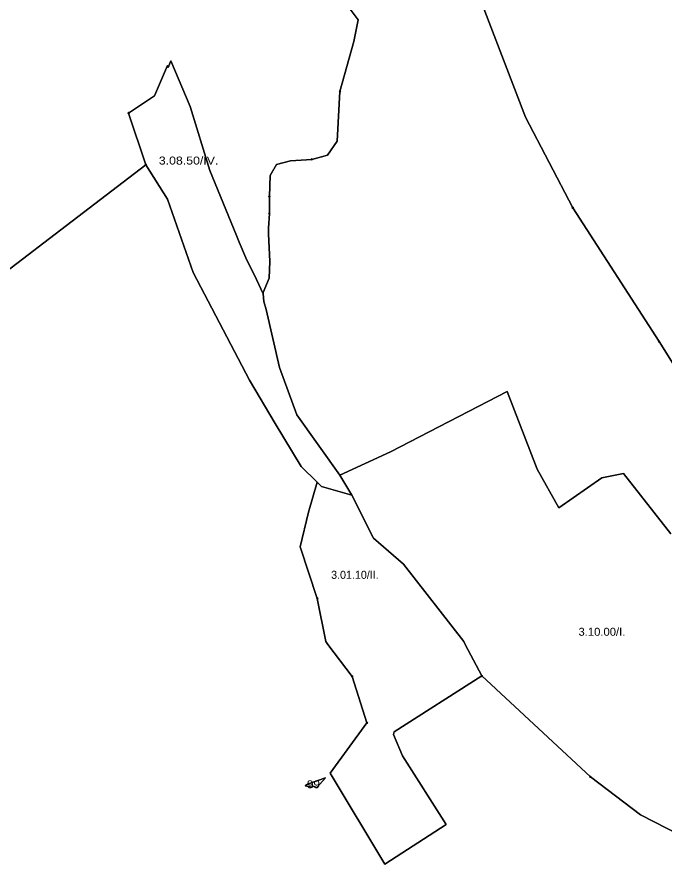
# Model space of a CAD drawing. Extents: x -650455 to -642254, y -1075222 to -1066610.
# Drawn here: x -647687 to -646878, y -1072281 to -1071216 of the extents above; entities that cross this region are included whole.
import ezdxf
from ezdxf.enums import TextEntityAlignment as Align

# ---------------------------------------------------------------- set-up
doc = ezdxf.new("R2010")
doc.units = 0
doc.header["$LTSCALE"] = 4
doc.header["$PDMODE"] = 32
doc.header["$PDSIZE"] = 2
for name, color, linetype, lineweight in [('1', 7, 'Continuous', 25), ('11', 7, 'Continuous', 13), ('12', 7, 'Continuous', 13), ('14', 7, 'Continuous', 13)]:
    doc.layers.add(name, color=color, linetype=linetype, lineweight=lineweight)
doc.layers.add('2', color=7, linetype='Continuous')

msp = doc.modelspace()

# ---------------------------------------------------------------- linework, layer by layer
at = {"layer": '1'}
for points in [[(-647412.981, -1071489.088), (-647446.149, -1071408.082), (-647470.706, -1071328.032), (-647494.813, -1071270.777), (-647498.258, -1071279.39), (-647499.23, -1071276.872), (-647515.389, -1071314.575), (-647547.706, -1071336.12), (-647526.161, -1071400.754), (-647800.855, -1071610.814), (-647801.949, -1071610.478), (-647870.875, -1071589.27), (-647903.192, -1071562.339), (-647919.351, -1071530.022), (-647913.965, -1071497.705), (-647903.192, -1071460.002), (-647881.648, -1071406.14), (-647897.806, -1071357.665), (-647773.924, -1071271.486), (-647788.736, -1071241.189), (-647806.937, -1071195.687)], [(-647277.051, -1071198.1), (-647260.893, -1071219.644), (-647266.279, -1071246.575), (-647283.784, -1071309.189), (-647287.224, -1071371.123), (-647299.444, -1071388.627), (-647318.899, -1071394.049), (-647345.688, -1071395.963), (-647362.91, -1071400.428), (-647370.883, -1071414.141), (-647371.84, -1071440.612), (-647371.84, -1071461.661), (-647372.796, -1071479.84), (-647372.796, -1071487.175), (-647371.521, -1071521.618), (-647372.159, -1071542.667), (-647379.813, -1071560.208), (-647379.646, -1071562.215), (-647388.105, -1071543.943), (-647401.5, -1071517.154), (-647409.473, -1071497.38), (-647412.981, -1071489.088)], [(-646870.396, -1071861.944), (-646929.643, -1071786.538), (-646956.574, -1071791.924), (-647010.436, -1071829.627), (-647037.367, -1071781.152), (-647075.07, -1071684.201), (-647220.496, -1071759.607), (-647283.784, -1071788.558), (-647337.645, -1071713.152), (-647359.19, -1071653.904), (-647375.906, -1071581.469), (-647378.856, -1071571.689), (-647379.646, -1071562.215), (-647379.813, -1071560.208), (-647372.159, -1071542.667), (-647371.521, -1071521.618), (-647372.796, -1071487.175), (-647372.796, -1071479.84), (-647371.84, -1071461.661), (-647371.84, -1071440.612), (-647370.883, -1071414.141), (-647362.91, -1071400.428), (-647345.688, -1071395.963), (-647318.899, -1071394.049), (-647299.444, -1071388.627), (-647287.224, -1071371.123), (-647283.784, -1071309.189), (-647266.279, -1071246.575), (-647260.893, -1071219.644), (-647277.051, -1071198.1)], [(-647052.179, -1071341.506), (-647104.694, -1071203.486)], [(-647104.694, -1071203.486), (-647052.179, -1071341.506), (-646992.931, -1071454.616), (-646885.208, -1071621.587), (-646804.415, -1071750.855)], [(-646804.415, -1071750.855), (-646885.208, -1071621.587), (-646992.931, -1071454.616), (-647052.179, -1071341.506)], [(-647800.855, -1071610.814), (-647526.161, -1071400.754), (-647499.23, -1071443.843), (-647466.913, -1071535.408), (-647396.893, -1071670.062), (-647364.576, -1071723.924)], [(-646859, -1072238.5), (-646908.5, -1072213.001), (-646971, -1072165.5), (-647106.5, -1072039.5), (-647127.153, -1072000), (-647128.931, -1071996.598), (-647204.338, -1071899.647), (-647242.041, -1071867.33), (-647268.972, -1071813.469), (-647283.784, -1071788.558), (-647220.496, -1071759.607), (-647075.07, -1071684.201), (-647037.367, -1071781.152), (-647010.436, -1071829.627), (-646956.574, -1071791.924), (-646929.643, -1071786.538), (-646870.396, -1071861.944)], [(-647364.576, -1071723.924), (-647332.259, -1071777.785), (-647312.093, -1071797.421)], [(-647312.093, -1071797.421), (-647322.833, -1071835.013), (-647333.606, -1071878.103), (-647312.061, -1071942.737), (-647301.289, -1071996.598), (-647298.718, -1072000), (-647268.5, -1072040), (-647250, -1072098), (-647296, -1072161), (-647227.5, -1072274.5), (-647151, -1072225.001), (-647205.5, -1072139.501), (-647217, -1072112.5), (-647216, -1072109.5), (-647106.5, -1072039.5), (-646971, -1072165.5), (-646908.5, -1072213.001), (-646859, -1072238.5)]]:
    msp.add_lwpolyline(points, dxfattribs=at)
for points in [[(-647379.646, -1071562.215), (-647378.856, -1071571.689), (-647375.906, -1071581.469), (-647359.19, -1071653.904), (-647337.645, -1071713.152), (-647283.784, -1071788.558), (-647268.972, -1071813.469), (-647306.675, -1071802.696), (-647312.093, -1071797.421), (-647332.259, -1071777.785), (-647364.576, -1071723.924), (-647396.893, -1071670.062), (-647466.913, -1071535.408), (-647499.23, -1071443.843), (-647526.161, -1071400.754), (-647547.706, -1071336.12), (-647515.389, -1071314.575), (-647499.23, -1071276.872), (-647498.258, -1071279.39), (-647494.813, -1071270.777), (-647470.706, -1071328.032), (-647446.149, -1071408.082), (-647412.981, -1071489.088), (-647409.473, -1071497.38), (-647401.5, -1071517.154), (-647388.105, -1071543.943)], [(-647268.972, -1071813.469), (-647242.041, -1071867.33), (-647204.338, -1071899.647), (-647128.931, -1071996.598), (-647127.153, -1072000), (-647106.5, -1072039.5), (-647216, -1072109.5), (-647217, -1072112.5), (-647205.5, -1072139.501), (-647151, -1072225.001), (-647227.5, -1072274.5), (-647296, -1072161), (-647250, -1072098), (-647268.5, -1072040), (-647298.718, -1072000), (-647301.289, -1071996.598), (-647312.061, -1071942.737), (-647333.606, -1071878.103), (-647322.833, -1071835.013), (-647312.093, -1071797.421), (-647306.675, -1071802.696)], [(-647301.629, -1072166.951), (-647312.731, -1072178.69), (-647317.33, -1072176.99), (-647318.97, -1072178.43), (-647327.05, -1072176.85), (-647324.44, -1072174.5)], [(-647301.629, -1072166.951), (-647324.44, -1072174.5), (-647327.05, -1072176.85), (-647318.97, -1072178.43), (-647317.33, -1072176.99), (-647312.731, -1072178.69)]]:
    msp.add_lwpolyline(points, close=True, dxfattribs=at)
at = {"layer": '11'}
for points in [[(-647547.706, -1070654.771), (-647515.389, -1070730.177), (-647460.18, -1070837.227), (-647390.16, -1070966.495), (-647320.14, -1071068.832), (-647244.734, -1071176.555), (-647277.051, -1071198.1), (-647260.893, -1071219.644), (-647266.279, -1071246.575), (-647283.784, -1071309.189), (-647287.224, -1071371.123), (-647299.444, -1071388.627), (-647318.899, -1071394.049), (-647345.688, -1071395.963), (-647362.91, -1071400.428), (-647370.883, -1071414.141), (-647371.84, -1071440.612), (-647371.84, -1071461.661)], [(-646992.931, -1071454.616), (-647052.179, -1071341.506), (-647104.694, -1071203.486), (-647131.625, -1071160.397), (-647158.555, -1071128.08), (-647180.1, -1071041.901), (-647207.031, -1070971.881)], [(-647526.161, -1071400.754), (-647800.855, -1071610.814), (-647801.949, -1071610.478), (-647799.782, -1071650.366), (-647789.455, -1071675.321), (-647779.56, -1071698.124), (-647786.013, -1071719.637), (-647794.619, -1071750.616), (-647797.63, -1071786.328), (-647789.455, -1071836.453), (-647780.85, -1071882.921), (-647775.687, -1071897.12), (-647747.29, -1071974.351), (-647744.278, -1072000.167), (-647701.628, -1072109.378), (-647917.5, -1072238.5), (-647970, -1072276), (-647994, -1072324), (-648000.504, -1072347.414)], [(-647312.061, -1071942.737), (-647333.606, -1071878.103), (-647322.833, -1071835.013), (-647312.093, -1071797.421), (-647332.259, -1071777.785), (-647364.576, -1071723.924), (-647396.893, -1071670.062), (-647466.913, -1071535.408), (-647499.23, -1071443.843), (-647526.161, -1071400.754)], [(-646698.038, -1071931.964), (-646735.742, -1071888.875), (-646762.673, -1071818.855), (-646804.415, -1071750.855), (-646885.208, -1071621.587), (-646992.931, -1071454.616)], [(-647371.84, -1071461.661), (-647372.796, -1071479.84), (-647372.796, -1071487.175), (-647371.521, -1071521.618), (-647372.159, -1071542.667), (-647379.813, -1071560.208), (-647379.646, -1071562.215), (-647378.856, -1071571.689), (-647375.906, -1071581.469), (-647359.19, -1071653.904), (-647337.645, -1071713.152), (-647283.784, -1071788.558), (-647220.496, -1071759.607), (-647075.07, -1071684.201), (-647037.367, -1071781.152), (-647010.436, -1071829.627), (-646956.574, -1071791.924), (-646929.643, -1071786.538), (-646870.396, -1071861.944)], [(-646870.396, -1071861.944), (-646929.643, -1071786.538), (-646956.574, -1071791.924), (-647010.436, -1071829.627), (-647037.367, -1071781.152), (-647075.07, -1071684.201), (-647220.496, -1071759.607), (-647283.784, -1071788.558), (-647268.972, -1071813.469), (-647242.041, -1071867.33), (-647204.338, -1071899.647), (-647128.931, -1071996.598)], [(-647106.5, -1072039.5), (-647216, -1072109.5), (-647217, -1072112.5), (-647205.5, -1072139.501), (-647151, -1072225.001), (-647227.5, -1072274.5), (-647296, -1072161), (-647250, -1072098), (-647268.5, -1072040), (-647298.718, -1072000), (-647301.289, -1071996.598), (-647312.061, -1071942.737)], [(-647128.931, -1071996.598), (-647127.153, -1072000), (-647106.5, -1072039.5), (-646971, -1072165.5)], [(-646725, -1072227.5), (-646766, -1072244.501), (-646794, -1072249.501), (-646830.5, -1072247), (-646859, -1072238.5), (-646908.5, -1072213.001), (-646971, -1072165.5), (-647106.5, -1072039.5)], [(-646971, -1072165.5), (-646908.5, -1072213.001), (-646859, -1072238.5)]]:
    msp.add_lwpolyline(points, dxfattribs=at)
for p in [(-647526.161, -1071400.754), (-646992.931, -1071454.616), (-647371.84, -1071461.661), (-647312.061, -1071942.737), (-647106.5, -1072039.5), (-646971, -1072165.5)]:
    msp.add_point(p, dxfattribs=at)
at = {"layer": '12'}
msp.add_line((-647268.5, -1072040), (-647250, -1072098), dxfattribs=at)
for points in [[(-647283.784, -1071309.189), (-647266.279, -1071246.575), (-647260.893, -1071219.644), (-647277.051, -1071198.1), (-647244.734, -1071176.555), (-647320.14, -1071068.832), (-647390.16, -1070966.495), (-647460.18, -1070837.227), (-647515.389, -1070730.177), (-647547.706, -1070654.771), (-647558.478, -1070606.295), (-647585.409, -1070514.73), (-647601.567, -1070433.938), (-647606.954, -1070347.759), (-647628.498, -1070288.512)], [(-647547.706, -1071336.12), (-647515.389, -1071314.575), (-647499.23, -1071276.872), (-647498.258, -1071279.39), (-647494.813, -1071270.777), (-647470.706, -1071328.032), (-647446.149, -1071408.082), (-647412.981, -1071489.088), (-647409.473, -1071497.38), (-647401.5, -1071517.154), (-647388.105, -1071543.943), (-647379.646, -1071562.215), (-647379.813, -1071560.208), (-647372.159, -1071542.667), (-647371.521, -1071521.618), (-647372.796, -1071487.175), (-647372.796, -1071479.84), (-647371.84, -1071461.661), (-647371.84, -1071440.612)], [(-647318.899, -1071394.049), (-647299.444, -1071388.627), (-647287.224, -1071371.123), (-647283.784, -1071309.189)], [(-647800.855, -1071610.814), (-647526.161, -1071400.754), (-647547.706, -1071336.12)], [(-647371.84, -1071440.612), (-647370.883, -1071414.141), (-647362.91, -1071400.428), (-647345.688, -1071395.963), (-647318.899, -1071394.049)], [(-647250, -1072098), (-647296, -1072161), (-647227.5, -1072274.5), (-647151, -1072225.001), (-647205.5, -1072139.501), (-647217, -1072112.5), (-647216, -1072109.5), (-647106.5, -1072039.5), (-647127.153, -1072000), (-647128.931, -1071996.598), (-647204.338, -1071899.647), (-647242.041, -1071867.33), (-647268.972, -1071813.469), (-647306.675, -1071802.696), (-647312.093, -1071797.421), (-647322.833, -1071835.013), (-647333.606, -1071878.103), (-647312.061, -1071942.737), (-647301.289, -1071996.598), (-647298.718, -1072000), (-647268.5, -1072040)]]:
    msp.add_lwpolyline(points, dxfattribs=at)
for p in [(-647283.784, -1071309.189), (-647547.706, -1071336.12), (-647318.899, -1071394.049), (-647371.84, -1071440.612), (-647268.5, -1072040), (-647250, -1072098)]:
    msp.add_point(p, dxfattribs=at)
at = {"layer": '14'}
msp.add_line((-646885.208, -1071621.587), (-646804.415, -1071750.855), dxfattribs=at)
msp.add_lwpolyline([(-647158.555, -1071128.08), (-647131.625, -1071160.397), (-647104.694, -1071203.486), (-647052.179, -1071341.506), (-646992.931, -1071454.616), (-646885.208, -1071621.587)], dxfattribs=at)
msp.add_lwpolyline([(-647466.913, -1071535.408), (-647396.893, -1071670.062), (-647364.576, -1071723.924), (-647332.259, -1071777.785), (-647312.093, -1071797.421), (-647306.675, -1071802.696), (-647268.972, -1071813.469), (-647283.784, -1071788.558), (-647337.645, -1071713.152), (-647359.19, -1071653.904), (-647375.906, -1071581.469), (-647378.856, -1071571.689), (-647379.646, -1071562.215), (-647388.105, -1071543.943), (-647401.5, -1071517.154), (-647409.473, -1071497.38), (-647412.981, -1071489.088), (-647446.149, -1071408.082), (-647470.706, -1071328.032), (-647494.813, -1071270.777), (-647498.258, -1071279.39), (-647499.23, -1071276.872), (-647515.389, -1071314.575), (-647547.706, -1071336.12), (-647526.161, -1071400.754), (-647499.23, -1071443.843)], close=True, dxfattribs=at)
msp.add_point((-646885.208, -1071621.587), dxfattribs=at)

# ---------------------------------------------------------------- texts
at = {"layer": '2'}
for s, width, p in [('3.08.50/IV.', 1.15, (-647472.772, -1071400.523)), ('3.10.00/I.', 1.05, (-646956.534, -1071989.283)), ('99', 1.1, (-647316.831, -1072179.886))]:
    msp.add_text(s, height=10, dxfattribs=dict(at, width=width)).set_placement(p, align=Align.CENTER)
msp.add_text('3.01.10/II.', height=10, dxfattribs=at).set_placement((-647265.052, -1071918.102), align=Align.CENTER)

doc.saveas('drawing.dxf')
